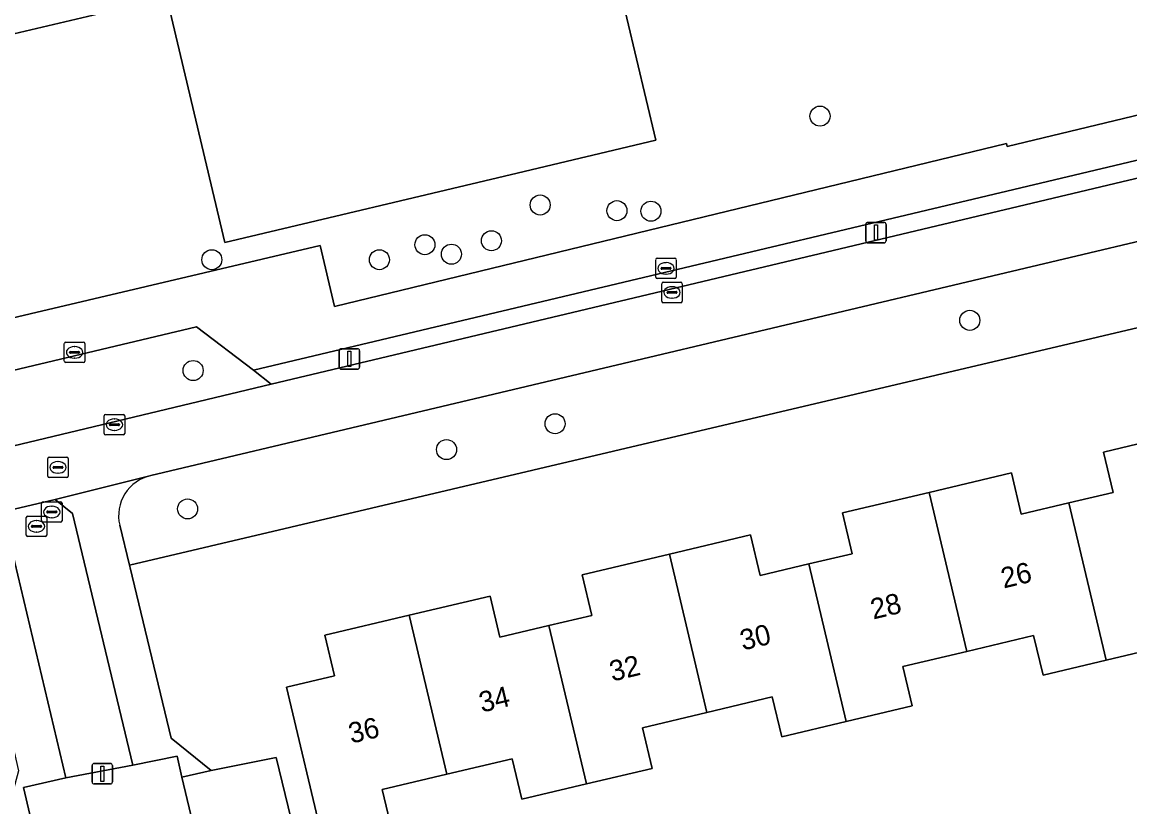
# Model space of a CAD drawing. Extents: x 158031 to 159244, y 380104 to 381214.
# Drawn here: x 158631 to 158685, y 380632.6 to 380670.9 of the extents above; entities that cross this region are included whole.
import ezdxf

# ---------------------------------------------------------------- set-up
doc = ezdxf.new("R2010")
doc.units = 0
for name, color, linetype in [('IMGEO_Berm_groen', 7, 'Continuous'), ('IMGEO_Boom', 7, 'Continuous'), ('IMGEO_Erf', 7, 'Continuous'), ('IMGEO_Fietspad_open', 7, 'Continuous'), ('IMGEO_Groenvoorziening', 7, 'Continuous'), ('IMGEO_Hek', 7, 'Continuous'), ('IMGEO_Kolk', 7, 'Continuous'), ('IMGEO_Lichtmast', 7, 'Continuous'), ('IMGEO_Pand', 7, 'Continuous'), ('IMGEO_Pand_nummerreeks', 7, 'Continuous'), ('IMGEO_Parkeervlak_open', 7, 'Continuous'), ('IMGEO_Rijbaan_lokaal_open', 7, 'Continuous'), ('IMGEO_Rioolput', 7, 'Continuous'), ('IMGEO_Verkeerseiland_open', 7, 'Continuous'), ('IMGEO_Voetpad_open', 7, 'Continuous')]:
    doc.layers.add(name, color=color, linetype=linetype)

msp = doc.modelspace()

# ---------------------------------------------------------------- linework, layer by layer
at = {"layer": 'IMGEO_Berm_groen'}
for points in [[(158643.138, 380653.223), (158642.266, 380653.921), (158639.496, 380656.032), (158628.532, 380653.422), (158629.34, 380649.935)], [(158633.446, 380646.922), (158632.592, 380647.598), (158630.034, 380647.004), (158633.114, 380634.023), (158636.393, 380634.638)]]:
    msp.add_lwpolyline(points, close=True, dxfattribs=at)
at = {"layer": 'IMGEO_Boom'}
for centre in [(158669.922, 380666.31), (158656.265, 380661.974), (158660.012, 380661.697), (158661.672, 380661.672), (158650.639, 380660.037), (158653.886, 380660.232), (158651.933, 380659.573), (158640.241, 380659.305), (158648.418, 380659.305), (158677.232, 380656.345), (158639.327, 380653.895), (158656.99, 380651.301), (158651.695, 380650.037), (158639.059, 380647.143)]:
    msp.add_circle(centre, 0.489, dxfattribs=at)
at = {"layer": 'IMGEO_Erf'}
msp.add_lwpolyline([(158686.881, 380718.056), (158686.652, 380719.032), (158670.862, 380715.31), (158649.457, 380710.132), (158646.034, 380709.321), (158573.471, 380692.129), (158581.882, 380657.767), (158585.545, 380642.697), (158606.222, 380647.594), (158605.611, 380650.592), (158645.531, 380659.999), (158646.233, 380657.02), (158679.017, 380664.973), (158679.063, 380664.833), (158698.247, 380669.444), (158698.093, 380670.277)], close=True, dxfattribs=at)
for points in [[(158660.028, 380673.097), (158661.915, 380665.137), (158655.137, 380663.53), (158640.878, 380660.15), (158638.047, 380672.1), (158625.302, 380669.083), (158626.576, 380663.712), (158615.937, 380661.19), (158615.092, 380664.758), (158616.105, 380664.998), (158615.63, 380667.004), (158614.617, 380666.765), (158610.51, 380665.792), (158608.951, 380672.369)], [(158703.146, 380660.152), (158636.227, 380644.398), (158636.257, 380644.275), (158638.262, 380635.957), (158640.207, 380634.374), (158643.384, 380635.009), (158646.891, 380620.567), (158649.038, 380621.183), (158650.241, 380621.462), (158649.596, 380624.187), (158653.719, 380625.164), (158657.846, 380626.142), (158658.489, 380623.417), (158662.878, 380624.462), (158662.235, 380627.187), (158666.432, 380628.177), (158670.63, 380629.168), (158671.273, 380626.443), (158675.658, 380627.472), (158675.009, 380630.195), (158679.175, 380631.189), (158683.342, 380632.182), (158683.991, 380629.458), (158688.336, 380630.486)], [(158645.717, 380630.694), (158643.881, 380638.444), (158646.222, 380638.999), (158645.752, 380640.98), (158649.878, 380641.958), (158653.821, 380642.892), (158654.297, 380640.883), (158656.695, 380641.451), (158658.781, 380641.945), (158658.312, 380643.925), (158662.57, 380644.934), (158666.525, 380645.871), (158666.994, 380643.889), (158669.381, 380644.455), (158671.485, 380644.953), (158671.012, 380646.948), (158675.253, 380647.952), (158679.262, 380648.902), (158679.739, 380646.89), (158682.071, 380647.442), (158684.223, 380647.952), (158683.757, 380649.92), (158687.949, 380650.914)], [(158687.116, 380640.519), (158683.888, 380639.754), (158680.805, 380639.024), (158680.346, 380640.961), (158677.088, 380640.189), (158673.97, 380639.451), (158674.425, 380637.527), (158671.2, 380636.763), (158668.053, 380636.017), (158667.591, 380637.968), (158664.395, 380637.211), (158661.256, 380636.467), (158661.726, 380634.483), (158658.522, 380633.724), (158655.366, 380632.976), (158654.897, 380634.953), (158651.711, 380634.198), (158648.553, 380633.45), (158649.021, 380631.477)]]:
    msp.add_lwpolyline(points, dxfattribs=at)
at = {"layer": 'IMGEO_Fietspad_open'}
for points in [[(158696.009, 380665.807), (158643.138, 380653.223), (158629.34, 380649.935), (158627.43, 380649.482), (158614.401, 380646.377), (158579.653, 380638.172), (158540.516, 380628.901), (158516.204, 380623.141), (158513.405, 380622.477), (158513.999, 380619.504), (158577.006, 380634.495), (158580.413, 380635.282), (158623.804, 380645.539), (158625.123, 380645.847), (158627.976, 380646.522), (158630.034, 380647.004), (158632.592, 380647.598), (158637.143, 380648.746), (158637.266, 380648.766), (158699.836, 380663.612)], [(158637.266, 380648.766), (158637.143, 380648.746), (158632.592, 380647.598), (158633.446, 380646.922), (158636.393, 380634.638), (158638.542, 380635.083), (158638.772, 380634.056), (158640.207, 380634.374), (158638.262, 380635.957), (158636.257, 380644.275)], [(158636.257, 380644.275), (158636.227, 380644.398), (158635.745, 380646.353)]]:
    msp.add_lwpolyline(points, dxfattribs=at)
msp.add_arc((158637.689, 380646.814), 1.998, 102.2205, 193.3301, dxfattribs=at)
at = {"layer": 'IMGEO_Groenvoorziening'}
msp.add_lwpolyline([(158635.745, 380646.353), (158636.227, 380644.398), (158703.146, 380660.152), (158699.836, 380663.612), (158637.266, 380648.766)], dxfattribs=at)
msp.add_arc((158637.689, 380646.814), 1.998, 102.2205, 193.3301, dxfattribs=at)
at = {"layer": 'IMGEO_Hek'}
for points in [[(158698.247, 380669.444), (158679.063, 380664.833), (158679.017, 380664.973), (158646.233, 380657.02), (158645.531, 380659.999), (158605.611, 380650.592), (158606.222, 380647.594), (158585.545, 380642.697), (158581.882, 380657.767)], [(158640.207, 380634.374), (158638.262, 380635.957), (158636.257, 380644.275)], [(158646.891, 380620.567), (158643.384, 380635.009), (158640.207, 380634.374)]]:
    msp.add_lwpolyline(points, dxfattribs=at)
at = {"layer": 'IMGEO_Kolk'}
for p, q in [((158661.98, 380659.38), (158662.832, 380659.38)), ((158661.905, 380658.454), (158661.905, 380659.306)), ((158662.164, 380658.874), (158662.164, 380658.886)), ((158662.602, 380658.837), (158662.204, 380658.837)), ((158662.207, 380658.923), (158662.605, 380658.923)), ((158662.393, 380659.16), (158662.418, 380659.16)), ((158662.648, 380658.886), (158662.648, 380658.874)), ((158662.906, 380659.306), (158662.906, 380658.454)), ((158662.832, 380658.38), (158661.98, 380658.38)), ((158662.416, 380658.6), (158662.391, 380658.6)), ((158662.199, 380657.281), (158662.199, 380658.133)), ((158662.274, 380658.207), (158663.126, 380658.207)), ((158662.458, 380657.701), (158662.458, 380657.713)), ((158662.501, 380657.75), (158662.899, 380657.75)), ((158662.687, 380657.987), (158662.712, 380657.987)), ((158662.942, 380657.713), (158662.942, 380657.701)), ((158663.2, 380658.133), (158663.2, 380657.281)), ((158663.126, 380657.207), (158662.274, 380657.207)), ((158662.896, 380657.664), (158662.498, 380657.664)), ((158662.71, 380657.427), (158662.685, 380657.427)), ((158633.042, 380654.355), (158633.042, 380655.207)), ((158633.117, 380655.281), (158633.969, 380655.281)), ((158633.53, 380655.061), (158633.555, 380655.061)), ((158634.043, 380655.207), (158634.043, 380654.355)), ((158633.301, 380654.775), (158633.301, 380654.787)), ((158633.739, 380654.738), (158633.341, 380654.738)), ((158633.344, 380654.824), (158633.742, 380654.824)), ((158633.553, 380654.501), (158633.528, 380654.501)), ((158633.785, 380654.787), (158633.785, 380654.775)), ((158633.969, 380654.281), (158633.117, 380654.281)), ((158634.987, 380650.828), (158634.987, 380651.68)), ((158635.062, 380651.754), (158635.914, 380651.754)), ((158635.246, 380651.248), (158635.246, 380651.26)), ((158635.289, 380651.297), (158635.687, 380651.297)), ((158635.475, 380651.534), (158635.5, 380651.534)), ((158635.73, 380651.26), (158635.73, 380651.248)), ((158635.988, 380651.68), (158635.988, 380650.828)), ((158635.914, 380650.754), (158635.062, 380650.754)), ((158635.684, 380651.211), (158635.286, 380651.211)), ((158635.498, 380650.974), (158635.473, 380650.974))]:
    msp.add_line(p, q, dxfattribs=at)
for points in [[(158661.98, 380659.38), (158662.832, 380659.38)], [(158661.905, 380658.454), (158661.905, 380659.306)], [(158662.906, 380659.306), (158662.906, 380658.454)], [(158662.832, 380658.38), (158661.98, 380658.38)], [(158662.199, 380657.281), (158662.199, 380658.133)], [(158662.274, 380658.207), (158663.126, 380658.207)], [(158663.2, 380658.133), (158663.2, 380657.281)], [(158663.126, 380657.207), (158662.274, 380657.207)], [(158633.042, 380654.355), (158633.042, 380655.207)], [(158633.117, 380655.281), (158633.969, 380655.281)], [(158634.043, 380655.207), (158634.043, 380654.355)], [(158633.969, 380654.281), (158633.117, 380654.281)], [(158634.987, 380650.828), (158634.987, 380651.68)], [(158635.062, 380651.754), (158635.914, 380651.754)], [(158635.988, 380651.68), (158635.988, 380650.828)], [(158635.914, 380650.754), (158635.062, 380650.754)]]:
    msp.add_lwpolyline(points, dxfattribs=at)
for centre, radius, start, end in [((158661.982, 380659.304), 0.0765, 91.552, 178.448), ((158661.982, 380659.304), 0.0765, 91.552, 178.448), ((158662.83, 380659.304), 0.0765, 1.552, 88.448), ((158662.83, 380659.304), 0.0765, 1.552, 88.448), ((158662.204, 380658.883), 0.0403, 85.8775, 175.7526), ((158662.201, 380658.873), 0.0366, 178.938, 274.7102), ((158662.605, 380658.88), 0.043, 264.8664, 352.4533), ((158662.609, 380658.885), 0.0386, 1.7309, 96.639), ((158661.982, 380658.456), 0.0765, 181.552, 268.448), ((158661.982, 380658.456), 0.0765, 181.552, 268.448), ((158662.83, 380658.456), 0.0765, 271.552, 358.448), ((158662.83, 380658.456), 0.0765, 271.552, 358.448), ((158662.276, 380658.131), 0.0765, 91.552, 178.448), ((158662.276, 380658.131), 0.0765, 91.552, 178.448), ((158662.498, 380657.71), 0.0403, 85.8775, 175.7526), ((158662.903, 380657.712), 0.0386, 1.7309, 96.639), ((158663.124, 380658.131), 0.0765, 1.552, 88.448), ((158663.124, 380658.131), 0.0765, 1.552, 88.448), ((158662.276, 380657.283), 0.0765, 181.552, 268.448), ((158662.276, 380657.283), 0.0765, 181.552, 268.448), ((158662.495, 380657.7), 0.0366, 178.938, 274.7102), ((158662.899, 380657.707), 0.043, 264.8664, 352.4533), ((158663.124, 380657.283), 0.0765, 271.552, 358.448), ((158663.124, 380657.283), 0.0765, 271.552, 358.448), ((158633.119, 380655.205), 0.0765, 91.552, 178.448), ((158633.119, 380655.205), 0.0765, 91.552, 178.448), ((158633.967, 380655.205), 0.0765, 1.552, 88.448), ((158633.967, 380655.205), 0.0765, 1.552, 88.448), ((158633.341, 380654.784), 0.0403, 85.8775, 175.7526), ((158633.338, 380654.774), 0.0366, 178.938, 274.7102), ((158633.742, 380654.781), 0.043, 264.8664, 352.4533), ((158633.746, 380654.786), 0.0386, 1.7309, 96.639), ((158633.119, 380654.357), 0.0765, 181.552, 268.448), ((158633.119, 380654.357), 0.0765, 181.552, 268.448), ((158633.967, 380654.357), 0.0765, 271.552, 358.448), ((158633.967, 380654.357), 0.0765, 271.552, 358.448), ((158635.064, 380651.678), 0.0765, 91.552, 178.448), ((158635.064, 380651.678), 0.0765, 91.552, 178.448), ((158635.286, 380651.257), 0.0403, 85.8775, 175.7526), ((158635.283, 380651.247), 0.0366, 178.938, 274.7102), ((158635.687, 380651.254), 0.043, 264.8664, 352.4533), ((158635.691, 380651.259), 0.0386, 1.7309, 96.639), ((158635.912, 380651.678), 0.0765, 1.552, 88.448), ((158635.912, 380651.678), 0.0765, 1.552, 88.448), ((158635.064, 380650.83), 0.0765, 181.552, 268.448), ((158635.064, 380650.83), 0.0765, 181.552, 268.448), ((158635.912, 380650.83), 0.0765, 271.552, 358.448), ((158635.912, 380650.83), 0.0765, 271.552, 358.448)]:
    msp.add_arc(centre, radius, start, end, dxfattribs=at)
for centre, major_axis, ratio, start_param, end_param in [((158662.392, 380658.88), (-0.387, 0.002), 0.722429, 4.712389, 7.853982), ((158662.417, 380658.88), (-0.39, 0.002), 0.717154, 1.570796, 4.712389), ((158662.686, 380657.707), (-0.387, 0.002), 0.722429, 4.712389, 7.853982), ((158662.711, 380657.707), (-0.39, 0.002), 0.717154, 1.570796, 4.712389), ((158633.529, 380654.781), (-0.387, 0.002), 0.722429, 4.712389, 7.853982), ((158633.554, 380654.781), (-0.39, 0.002), 0.717154, 1.570796, 4.712389), ((158635.474, 380651.254), (-0.387, 0.002), 0.722429, 4.712389, 7.853982), ((158635.499, 380651.254), (-0.39, 0.002), 0.717154, 1.570796, 4.712389)]:
    msp.add_ellipse(centre, major_axis=major_axis, ratio=ratio, start_param=start_param, end_param=end_param, dxfattribs=at)
at = {"layer": 'IMGEO_Lichtmast'}
for p, q in [((158672.155, 380660.225), (158672.155, 380661.025)), ((158672.155, 380661.025), (158672.155, 380660.225)), ((158672.255, 380661.125), (158673.045, 380661.125)), ((158673.045, 380661.125), (158672.255, 380661.125)), ((158673.145, 380661.025), (158673.145, 380660.225)), ((158673.145, 380660.225), (158673.145, 380661.025)), ((158673.045, 380660.125), (158672.255, 380660.125)), ((158672.255, 380660.125), (158673.045, 380660.125)), ((158646.46, 380654.06), (158646.46, 380654.86)), ((158646.46, 380654.86), (158646.46, 380654.06)), ((158646.56, 380654.96), (158647.35, 380654.96)), ((158647.35, 380654.96), (158646.56, 380654.96)), ((158647.45, 380654.86), (158647.45, 380654.06)), ((158647.45, 380654.06), (158647.45, 380654.86)), ((158647.35, 380653.96), (158646.56, 380653.96)), ((158646.56, 380653.96), (158647.35, 380653.96)), ((158634.398, 380633.822), (158634.398, 380634.622)), ((158634.398, 380634.622), (158634.398, 380633.822)), ((158634.498, 380634.722), (158635.288, 380634.722)), ((158635.288, 380634.722), (158634.498, 380634.722)), ((158635.388, 380634.622), (158635.388, 380633.822)), ((158635.388, 380633.822), (158635.388, 380634.622)), ((158635.288, 380633.722), (158634.498, 380633.722)), ((158634.498, 380633.722), (158635.288, 380633.722))]:
    msp.add_line(p, q, dxfattribs=at)
for points in [[(158672.575, 380661), (158672.725, 380661), (158672.725, 380660.25), (158672.575, 380660.25), (158672.575, 380661)], [(158646.88, 380654.835), (158647.03, 380654.835), (158647.03, 380654.085), (158646.88, 380654.085), (158646.88, 380654.835)], [(158634.818, 380634.597), (158634.968, 380634.597), (158634.968, 380633.847), (158634.818, 380633.847), (158634.818, 380634.597)]]:
    msp.add_lwpolyline(points, dxfattribs=at)
for centre, start, end in [((158672.255, 380661.025), 90, 180), ((158672.255, 380661.025), 90, 180), ((158673.045, 380661.025), 0, 90), ((158673.045, 380661.025), 360, 90), ((158672.255, 380660.225), 180, 270), ((158672.255, 380660.225), 180, 270), ((158673.045, 380660.225), 270, 0), ((158673.045, 380660.225), 270, 0), ((158646.56, 380654.86), 90, 180), ((158646.56, 380654.86), 90, 180), ((158647.35, 380654.86), 0, 90), ((158647.35, 380654.86), 360, 90), ((158646.56, 380654.06), 180, 270), ((158646.56, 380654.06), 180, 270), ((158647.35, 380654.06), 270, 0), ((158647.35, 380654.06), 270, 0), ((158634.498, 380634.622), 90, 180), ((158634.498, 380634.622), 90, 180), ((158635.288, 380634.622), 0, 90), ((158635.288, 380634.622), 360, 90), ((158634.498, 380633.822), 180, 270), ((158634.498, 380633.822), 180, 270), ((158635.288, 380633.822), 270, 0), ((158635.288, 380633.822), 270, 0)]:
    msp.add_arc(centre, 0.1, start, end, dxfattribs=at)
at = {"layer": 'IMGEO_Pand'}
msp.add_lwpolyline([(158608.951, 380672.369), (158610.51, 380665.792), (158614.617, 380666.765), (158615.63, 380667.004), (158616.105, 380664.998), (158615.092, 380664.758), (158615.937, 380661.19), (158626.576, 380663.712), (158625.302, 380669.083), (158638.047, 380672.1), (158640.878, 380660.15), (158655.137, 380663.53), (158661.915, 380665.137), (158660.028, 380673.097)], dxfattribs=at)
for points in [[(158682.071, 380647.442), (158683.888, 380639.754), (158687.116, 380640.519), (158686.641, 380642.524), (158689.757, 380643.262), (158687.949, 380650.914), (158683.757, 380649.92), (158684.223, 380647.952)], [(158682.071, 380647.442), (158679.739, 380646.89), (158679.262, 380648.902), (158675.253, 380647.952), (158677.088, 380640.189), (158680.346, 380640.961), (158680.805, 380639.024), (158683.888, 380639.754)], [(158677.088, 380640.189), (158675.253, 380647.952), (158671.012, 380646.948), (158671.485, 380644.953), (158669.381, 380644.455), (158671.2, 380636.763), (158674.425, 380637.527), (158673.97, 380639.451)], [(158662.57, 380644.934), (158664.395, 380637.211), (158667.591, 380637.968), (158668.053, 380636.017), (158671.2, 380636.763), (158669.381, 380644.455), (158666.994, 380643.889), (158666.525, 380645.871)], [(158662.57, 380644.934), (158658.312, 380643.925), (158658.781, 380641.945), (158656.695, 380641.451), (158658.522, 380633.724), (158661.726, 380634.483), (158661.256, 380636.467), (158664.395, 380637.211)], [(158651.711, 380634.198), (158654.897, 380634.953), (158655.366, 380632.976), (158658.522, 380633.724), (158656.695, 380641.451), (158654.297, 380640.883), (158653.821, 380642.892), (158649.878, 380641.958)], [(158651.711, 380634.198), (158649.878, 380641.958), (158645.752, 380640.98), (158646.222, 380638.999), (158643.881, 380638.444), (158645.717, 380630.694), (158649.021, 380631.477), (158648.553, 380633.45)]]:
    msp.add_lwpolyline(points, close=True, dxfattribs=at)
at = {"layer": 'IMGEO_Parkeervlak_open'}
msp.add_lwpolyline([(158642.259, 380619.492), (158646.891, 380620.567), (158643.384, 380635.009), (158640.207, 380634.374), (158638.772, 380634.056)], close=True, dxfattribs=at)
at = {"layer": 'IMGEO_Rijbaan_lokaal_open'}
msp.add_lwpolyline([(158634.865, 380617.848), (158642.259, 380619.492), (158638.772, 380634.056), (158638.542, 380635.083), (158636.393, 380634.638), (158633.114, 380634.023), (158631.047, 380633.555), (158631.356, 380632.232)], close=True, dxfattribs=at)
at = {"layer": 'IMGEO_Rioolput'}
for p, q in [((158632.306, 380649.669), (158633.158, 380649.669)), ((158632.231, 380648.743), (158632.231, 380649.595)), ((158632.49, 380649.163), (158632.49, 380649.175)), ((158632.928, 380649.126), (158632.53, 380649.126)), ((158632.533, 380649.212), (158632.931, 380649.212)), ((158632.719, 380649.449), (158632.744, 380649.449)), ((158632.974, 380649.175), (158632.974, 380649.163)), ((158633.232, 380649.595), (158633.232, 380648.743)), ((158633.158, 380648.669), (158632.306, 380648.669)), ((158632.742, 380648.889), (158632.717, 380648.889)), ((158632.006, 380647.494), (158632.858, 380647.494)), ((158631.931, 380646.568), (158631.931, 380647.42)), ((158632.19, 380646.988), (158632.19, 380647)), ((158632.628, 380646.951), (158632.23, 380646.951)), ((158632.233, 380647.037), (158632.631, 380647.037)), ((158632.419, 380647.274), (158632.444, 380647.274)), ((158632.674, 380647), (158632.674, 380646.988)), ((158632.932, 380647.42), (158632.932, 380646.568)), ((158631.182, 380645.867), (158631.182, 380646.719)), ((158631.257, 380646.793), (158632.109, 380646.793)), ((158631.67, 380646.573), (158631.695, 380646.573)), ((158632.858, 380646.494), (158632.006, 380646.494)), ((158632.183, 380646.719), (158632.183, 380645.867)), ((158632.442, 380646.714), (158632.417, 380646.714)), ((158631.441, 380646.287), (158631.441, 380646.299)), ((158631.879, 380646.25), (158631.481, 380646.25)), ((158631.484, 380646.336), (158631.882, 380646.336)), ((158631.693, 380646.013), (158631.668, 380646.013)), ((158631.925, 380646.299), (158631.925, 380646.287)), ((158632.109, 380645.793), (158631.257, 380645.793))]:
    msp.add_line(p, q, dxfattribs=at)
for points in [[(158632.306, 380649.669), (158633.158, 380649.669)], [(158632.231, 380648.743), (158632.231, 380649.595)], [(158633.232, 380649.595), (158633.232, 380648.743)], [(158633.158, 380648.669), (158632.306, 380648.669)], [(158632.006, 380647.494), (158632.858, 380647.494)], [(158631.931, 380646.568), (158631.931, 380647.42)], [(158632.932, 380647.42), (158632.932, 380646.568)], [(158631.182, 380645.867), (158631.182, 380646.719)], [(158631.257, 380646.793), (158632.109, 380646.793)], [(158632.858, 380646.494), (158632.006, 380646.494)], [(158632.183, 380646.719), (158632.183, 380645.867)], [(158632.109, 380645.793), (158631.257, 380645.793)]]:
    msp.add_lwpolyline(points, dxfattribs=at)
for centre, radius, start, end in [((158632.308, 380649.593), 0.0765, 91.552, 178.448), ((158632.308, 380649.593), 0.0765, 91.552, 178.448), ((158633.156, 380649.593), 0.0765, 1.552, 88.448), ((158633.156, 380649.593), 0.0765, 1.552, 88.448), ((158632.53, 380649.172), 0.0403, 85.8775, 175.7526), ((158632.527, 380649.162), 0.0366, 178.938, 274.7102), ((158632.931, 380649.169), 0.043, 264.8664, 352.4533), ((158632.935, 380649.174), 0.0386, 1.7309, 96.639), ((158632.308, 380648.745), 0.0765, 181.552, 268.448), ((158632.308, 380648.745), 0.0765, 181.552, 268.448), ((158633.156, 380648.745), 0.0765, 271.552, 358.448), ((158633.156, 380648.745), 0.0765, 271.552, 358.448), ((158632.008, 380647.418), 0.0765, 91.552, 178.448), ((158632.008, 380647.418), 0.0765, 91.552, 178.448), ((158632.856, 380647.418), 0.0765, 1.552, 88.448), ((158632.856, 380647.418), 0.0765, 1.552, 88.448), ((158632.23, 380646.997), 0.0403, 85.8775, 175.7526), ((158632.227, 380646.987), 0.0366, 178.938, 274.7102), ((158632.631, 380646.994), 0.043, 264.8664, 352.4533), ((158632.635, 380646.999), 0.0386, 1.7309, 96.639), ((158631.259, 380646.717), 0.0765, 91.552, 178.448), ((158631.259, 380646.717), 0.0765, 91.552, 178.448), ((158632.008, 380646.57), 0.0765, 181.552, 268.448), ((158632.008, 380646.57), 0.0765, 181.552, 268.448), ((158632.107, 380646.717), 0.0765, 1.552, 88.448), ((158632.107, 380646.717), 0.0765, 1.552, 88.448), ((158632.856, 380646.57), 0.0765, 271.552, 358.448), ((158632.856, 380646.57), 0.0765, 271.552, 358.448), ((158631.259, 380645.869), 0.0765, 181.552, 268.448), ((158631.259, 380645.869), 0.0765, 181.552, 268.448), ((158631.481, 380646.296), 0.0403, 85.8775, 175.7526), ((158631.478, 380646.286), 0.0366, 178.938, 274.7102), ((158631.882, 380646.293), 0.043, 264.8664, 352.4533), ((158631.886, 380646.298), 0.0386, 1.7309, 96.639), ((158632.107, 380645.869), 0.0765, 271.552, 358.448), ((158632.107, 380645.869), 0.0765, 271.552, 358.448)]:
    msp.add_arc(centre, radius, start, end, dxfattribs=at)
for centre, major_axis, ratio, start_param, end_param in [((158632.718, 380649.169), (-0.387, 0.002), 0.722429, 4.712389, 7.853982), ((158632.743, 380649.169), (-0.39, 0.002), 0.717154, 1.570796, 4.712389), ((158632.418, 380646.994), (-0.387, 0.002), 0.722429, 4.712389, 7.853982), ((158632.443, 380646.994), (-0.39, 0.002), 0.717154, 1.570796, 4.712389), ((158631.669, 380646.293), (-0.387, 0.002), 0.722429, 4.712389, 7.853982), ((158631.694, 380646.293), (-0.39, 0.002), 0.717154, 1.570796, 4.712389)]:
    msp.add_ellipse(centre, major_axis=major_axis, ratio=ratio, start_param=start_param, end_param=end_param, dxfattribs=at)
at = {"layer": 'IMGEO_Verkeerseiland_open'}
msp.add_lwpolyline([(158696.009, 380665.807), (158695.817, 380666.633), (158642.266, 380653.921), (158643.138, 380653.223)], close=True, dxfattribs=at)
at = {"layer": 'IMGEO_Voetpad_open'}
for points in [[(158698.247, 380669.444), (158679.063, 380664.833), (158679.017, 380664.973), (158646.233, 380657.02), (158645.531, 380659.999), (158605.611, 380650.592), (158606.222, 380647.594), (158585.545, 380642.697), (158582.005, 380641.477), (158579.059, 380640.785), (158579.128, 380640.493), (158578.836, 380640.425), (158579.03, 380639.698), (158578.235, 380639.51), (158560.791, 380635.377), (158560.659, 380635.948), (158557.728, 380635.248)], [(158540.301, 380629.746), (158540.516, 380628.901), (158579.653, 380638.172), (158579.452, 380638.994), (158614.173, 380647.222), (158614.074, 380647.672), (158615.39, 380650.312), (158626.635, 380652.977), (158627.43, 380649.482), (158629.34, 380649.935), (158628.532, 380653.422), (158639.496, 380656.032), (158642.266, 380653.921), (158695.817, 380666.633), (158696.009, 380665.807)]]:
    msp.add_lwpolyline(points, dxfattribs=at)
msp.add_lwpolyline([(158630.034, 380647.004), (158627.976, 380646.522), (158628.853, 380642.842), (158628.933, 380642.507), (158630.8, 380634.354), (158630.155, 380631.932), (158631.356, 380632.232), (158631.047, 380633.555), (158633.114, 380634.023)], close=True, dxfattribs=at)

# ---------------------------------------------------------------- texts
at = {"layer": 'IMGEO_Pand_nummerreeks'}
for s, p in [('26', (158678.884, 380643.257)), ('28', (158672.52, 380641.744)), ('30', (158666.152, 380640.229)), ('32', (158659.779, 380638.713)), ('34', (158653.414, 380637.199)), ('36', (158647.046, 380635.685))]:
    msp.add_text(s, height=1, rotation=13.379, dxfattribs=at).set_placement(p)

doc.saveas('drawing.dxf')
